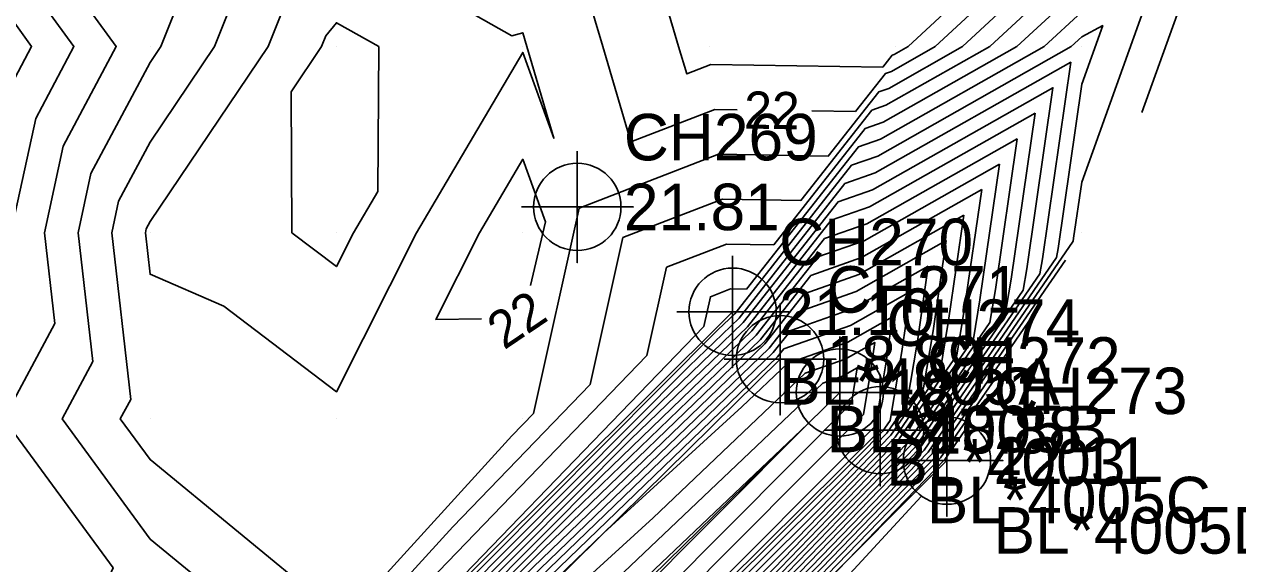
# Model space of a CAD drawing. Extents: x 2531902 to 2533249, y 715219 to 716099.
# Drawn here: x 2533033.2 to 2533098.4, y 715822.2 to 715851.2 of the extents above; entities that cross this region are included whole.
import ezdxf

# ---------------------------------------------------------------- set-up
doc = ezdxf.new("R2010")
doc.units = 0
for name, color, linetype in [('DTM Contours Major', 7, 'Continuous'), ('DTM Contours Major Text', 7, 'Continuous'), ('DTM Contours Minor', 7, 'Continuous'), ('Exist DTM Breakline', 7, 'Continuous'), ('Exist DTM Breakline Cogo Comment', 7, 'Continuous'), ('Exist DTM Breakline Cogo Elevation', 7, 'Continuous'), ('Exist DTM Breakline Cogo Number', 7, 'Continuous'), ('Exist DTM Breakline Cogo Point CELL', 7, 'Continuous'), ('Exist DTM Drainline', 7, 'Continuous'), ('Exist DTM Drainline Cogo Comment', 7, 'Continuous'), ('Exist DTM Drainline Cogo Elevation', 7, 'Continuous'), ('Exist DTM Drainline Cogo Number', 7, 'Continuous'), ('Exist DTM Drainline Cogo Point CELL', 7, 'Continuous'), ('Exist DTM QL2 LIDAR Elevation Point', 7, 'Continuous'), ('Exist DTM Regular Point CELL', 7, 'Continuous'), ('Exist DTM Regular Point Cogo Elevation', 7, 'Continuous'), ('Exist DTM Regular Point Cogo Number', 7, 'Continuous')]:
    doc.layers.add(name, color=color, linetype=linetype)

msp = doc.modelspace()

# ---------------------------------------------------------------- linework, layer by layer
at = {"layer": 'DTM Contours Major'}
for points in [[(2533075.512, 715846.541), (2533077.856, 715846.504), (2533079.467, 715848.554), (2533079.786, 715848.666), (2533082.141, 715850), (2533090, 715857.3), (2533095.009, 715860), (2533097.108, 715867.108), (2533098.179, 715870), (2533100, 715875.186), (2533111.816, 715879.234), (2533118.548, 715880.563)], [(2533041.774, 715810.454), (2533042.404, 715811.1), (2533043.161, 715818.289), (2533049.48, 715820), (2533040, 715827.811), (2533038.4, 715830), (2533038.956, 715831.044), (2533037.941, 715840), (2533038.308, 715841.692), (2533040, 715844.87), (2533043.452, 715850), (2533045.318, 715854.682), (2533049.57, 715860), (2533050, 715860.663), (2533051.38, 715861.38), (2533060, 715863.087), (2533062.327, 715860), (2533061.88, 715858.12), (2533064.295, 715850), (2533065.802, 715844.886), (2533070.3, 715846.623), (2533071.512, 715846.604)], [(2533055.198, 715819.396), (2533070.495, 715834.792), (2533071.376, 715835.643), (2533077.65, 715843.625), (2533079.056, 715844.119), (2533089.44, 715850), (2533090, 715850.52), (2533091.128, 715851.128), (2533090, 715847.981), (2533088.729, 715839.16), (2533088.647, 715838.672), (2533081.538, 715828.315), (2533066.066, 715812.328), (2533063.311, 715809.583)], [(2533057.677, 715840), (2533060, 715843.945), (2533061.222, 715840.578), (2533060.412, 715837.159)], [(2533085.587, 715843.684), (2533078.325, 715839.571), (2533075.832, 715838.696), (2533072.526, 715834.489), (2533062.673, 715824.977), (2533051.181, 715813.41), (2533041.576, 715804.106), (2533029.847, 715792.318), (2533029.205, 715791.695), (2533027.895, 715790.378), (2533015.561, 715777.627), (2533013.348, 715775.36)], [(2533082.375, 715831.659), (2533084.183, 715834.292), (2533084.535, 715836.387), (2533085.587, 715843.684)], [(2533057.787, 715835.38), (2533055.335, 715835.335), (2533057.677, 715840)], [(2533080.807, 715836.843), (2533077.595, 715835.024), (2533074.015, 715833.767), (2533073.676, 715833.335), (2533054.852, 715815.162), (2533052.148, 715812.44), (2533034.586, 715795.428), (2533030.67, 715791.493), (2533029.541, 715790.397), (2533029.097, 715789.95), (2533012.049, 715772.325), (2533009.123, 715768.142), (2533009.05, 715768.032)], [(2533048.953, 715798.969), (2533056.72, 715806.716), (2533058.104, 715808.153), (2533078.44, 715828.42), (2533079.316, 715829.326), (2533079.719, 715829.913), (2533080.342, 715833.615), (2533080.807, 715836.843)], [(2533083.724, 715829.377), (2533082.649, 715827.81), (2533076.89, 715821.859), (2533063.46, 715807.284), (2533061.198, 715804.899), (2533056.94, 715799.884), (2533056.737, 715799.66)], [(2533008.764, 715758.562), (2533009.843, 715760.678), (2533014.663, 715765.254), (2533014.672, 715765.262), (2533023.159, 715773.32), (2533037.158, 715784.95), (2533037.66, 715785.451), (2533038.413, 715786.237), (2533049.753, 715797.548), (2533059.385, 715807.549), (2533072.253, 715820.374), (2533080.039, 715828.42)]]:
    msp.add_lwpolyline(points, dxfattribs=at)
at = {"layer": 'DTM Contours Minor'}
for points in [[(2533029.47, 715797.174), (2533034.584, 715802), (2533044.323, 715811.978), (2533044.889, 715817.354), (2533050.003, 715818.738), (2533059.408, 715829.085), (2533060.57, 715830.291), (2533063.024, 715841.321), (2533070.513, 715844.213), (2533076.394, 715844.12), (2533079.104, 715847.569), (2533079.64, 715847.757), (2533083.601, 715850), (2533090, 715855.944), (2533097.525, 715860), (2533100, 715868.383)], [(2533032.179, 715798.448), (2533046.243, 715812.856), (2533046.618, 715816.418), (2533050.007, 715817.335), (2533056.239, 715824.192), (2533063.618, 715831.849), (2533065.373, 715839.735), (2533070.727, 715841.802), (2533074.931, 715841.736), (2533078.74, 715846.583), (2533079.494, 715846.847), (2533085.061, 715850), (2533090, 715854.588), (2533099.953, 715859.953)], [(2533067.676, 715852.324), (2533068.367, 715850), (2533068.798, 715848.536), (2533070.086, 715849.033), (2533079.318, 715848.888), (2533079.83, 715849.54), (2533079.932, 715849.576), (2533080.681, 715850), (2533090, 715858.655)], [(2533029.774, 715794.896), (2533048.162, 715813.734), (2533048.347, 715815.482), (2533050.01, 715815.933), (2533053.069, 715819.299), (2533066.666, 715833.407), (2533067.721, 715838.149), (2533070.941, 715839.392), (2533073.469, 715839.352), (2533078.377, 715845.597), (2533079.348, 715845.938), (2533086.52, 715850), (2533090, 715853.232), (2533097.012, 715857.012), (2533093.228, 715846.455)], [(2533030, 715800.68), (2533034.245, 715804.245), (2533039.393, 715809.104), (2533040.484, 715810.222), (2533041.432, 715819.225), (2533044.295, 715820), (2533040, 715823.539), (2533035.277, 715830), (2533036.919, 715833.081), (2533036.135, 715840), (2533036.825, 715843.175), (2533040, 715849.143), (2533040.577, 715850), (2533043.262, 715856.738)], [(2533030, 715804.336), (2533036.745, 715810), (2533033.616, 715816.384), (2533037.117, 715820), (2533038.009, 715821.991), (2533032.155, 715830), (2533034.882, 715835.118), (2533034.329, 715840), (2533035.341, 715844.659), (2533038.183, 715850), (2533034.175, 715855.527)], [(2533050, 715855.91), (2533047.374, 715852.626), (2533046.328, 715850), (2533040, 715840.598), (2533039.792, 715840.208), (2533039.747, 715840), (2533040, 715837.77), (2533043.949, 715836.051), (2533050, 715831.445), (2533054.295, 715840), (2533060, 715849.686), (2533061.673, 715845.079), (2533060.222, 715850), (2533060, 715850.748), (2533059.418, 715850.582), (2533050, 715855.91)], [(2533028.859, 715793.308), (2533049.964, 715814.518), (2533050.02, 715814.573), (2533051.407, 715815.969), (2533069.714, 715834.964), (2533070.069, 715836.563), (2533071.155, 715836.982), (2533072.007, 715836.969), (2533078.013, 715844.611), (2533079.202, 715845.028), (2533087.98, 715850), (2533090, 715851.876), (2533094.07, 715854.07), (2533090, 715842.716), (2533089.567, 715839.714), (2533089.539, 715839.548), (2533081.76, 715828.214), (2533064.829, 715810.719), (2533060.921, 715806.824), (2533041.394, 715786.547), (2533040.207, 715785.363), (2533038.711, 715783.801), (2533038.669, 715783.758), (2533033.901, 715779.797)], [(2533032.523, 715840), (2533033.857, 715846.143), (2533035.909, 715850), (2533033.015, 715853.991)], [(2533032.373, 715847.627), (2533033.636, 715850), (2533031.855, 715852.456)], [(2533047.563, 715847.563), (2533049.203, 715850), (2533049.43, 715850.57), (2533050, 715851.282), (2533052.267, 715850), (2533052.22, 715842.22), (2533050.913, 715840), (2533050, 715838.182), (2533047.612, 715840), (2533047.563, 715847.563)], [(2533029.188, 715792.978), (2533047.168, 715811.047), (2533050.407, 715814.185), (2533068.93, 715832.829), (2533071.606, 715835.412), (2533077.286, 715842.639), (2533078.91, 715843.209), (2533089.411, 715849.157), (2533087.89, 715838.605), (2533087.754, 715837.796), (2533081.316, 715828.416), (2533067.304, 715813.937), (2533060.409, 715807.066), (2533044.18, 715790.214), (2533039.609, 715785.654), (2533038.361, 715784.351), (2533038.165, 715784.155), (2533016.248, 715765.948)], [(2533029.353, 715792.813), (2533045.77, 715809.312), (2533050.6, 715813.991), (2533067.366, 715830.866), (2533071.836, 715835.181), (2533076.923, 715841.654), (2533078.764, 715842.3), (2533088.455, 715847.788), (2533087.051, 715838.051), (2533086.861, 715836.92), (2533081.093, 715828.517), (2533068.541, 715815.546), (2533060.153, 715807.187), (2533045.573, 715792.047), (2533039.31, 715785.8), (2533038.186, 715784.626), (2533037.914, 715784.354), (2533017.016, 715766.994)], [(2533019.064, 715769.102), (2533037.662, 715784.553), (2533038.011, 715784.901), (2533039.011, 715785.945), (2533046.967, 715793.881), (2533059.897, 715807.307), (2533069.778, 715817.156), (2533080.871, 715828.618), (2533085.968, 715836.044), (2533086.213, 715837.496), (2533087.499, 715846.42)], [(2533087.499, 715846.42), (2533078.617, 715841.39), (2533076.559, 715840.668), (2533072.066, 715834.951), (2533065.802, 715828.903), (2533050.794, 715813.798), (2533044.372, 715807.577), (2533029.518, 715792.648)], [(2533021.111, 715771.211), (2533037.41, 715784.751), (2533037.835, 715785.176), (2533038.712, 715786.091), (2533048.36, 715795.714), (2533059.641, 715807.428), (2533071.016, 715818.765), (2533080.649, 715828.719), (2533085.076, 715835.168), (2533085.374, 715836.942), (2533086.543, 715845.052)], [(2533086.543, 715845.052), (2533078.471, 715840.481), (2533076.196, 715839.682), (2533072.296, 715834.72), (2533064.238, 715826.94), (2533050.987, 715813.604), (2533042.974, 715805.841), (2533029.682, 715792.483)], [(2533025.207, 715775.429), (2533036.906, 715785.148), (2533037.485, 715785.726), (2533038.114, 715786.382), (2533051.147, 715799.382), (2533059.128, 715807.67), (2533073.49, 715821.983), (2533080.205, 715828.922), (2533083.29, 715833.416), (2533083.697, 715835.833), (2533084.631, 715842.315)], [(2533084.631, 715842.315), (2533078.179, 715838.662), (2533075.469, 715837.71), (2533072.756, 715834.258), (2533061.109, 715823.014), (2533051.374, 715813.216), (2533040.178, 715802.37), (2533030.011, 715792.153)], [(2533027.254, 715777.537), (2533036.655, 715785.347), (2533037.31, 715786.001), (2533037.815, 715786.528), (2533052.54, 715801.215), (2533058.872, 715807.791), (2533074.728, 715823.593), (2533079.983, 715829.023), (2533082.397, 715832.54), (2533082.858, 715835.279), (2533083.675, 715840.947)], [(2533083.675, 715840.947), (2533078.033, 715837.752), (2533075.106, 715836.724), (2533072.986, 715834.028), (2533059.545, 715821.051), (2533051.567, 715813.022), (2533038.78, 715800.635), (2533030.176, 715791.988)], [(2533029.302, 715779.646), (2533036.403, 715785.546), (2533037.135, 715786.276), (2533037.516, 715786.674), (2533053.933, 715803.049), (2533058.616, 715807.911), (2533075.965, 715825.202), (2533079.76, 715829.124), (2533081.504, 715831.665), (2533082.019, 715834.724), (2533082.719, 715839.579)], [(2533082.719, 715839.579), (2533077.887, 715836.843), (2533074.742, 715835.739), (2533073.216, 715833.797), (2533057.981, 715819.088), (2533051.761, 715812.828), (2533037.382, 715798.899), (2533030.341, 715791.823)], [(2533089.128, 715838.524), (2533081.982, 715828.113), (2533063.592, 715809.11), (2533061.177, 715806.704), (2533043.718, 715788.574), (2533040.95, 715785.525), (2533041.002, 715784.939), (2533040.368, 715784.644), (2533039.005, 715783.046), (2533032.907, 715774.504)], [(2533081.763, 715838.211), (2533077.741, 715835.933), (2533074.379, 715834.753), (2533073.446, 715833.566), (2533056.416, 715817.125), (2533051.954, 715812.634), (2533035.984, 715797.164), (2533030.505, 715791.658)], [(2533031.349, 715781.755), (2533036.151, 715785.744), (2533036.959, 715786.551), (2533037.217, 715786.819), (2533055.327, 715804.882), (2533058.36, 715808.032), (2533077.202, 715826.811), (2533079.538, 715829.225), (2533080.612, 715830.789), (2533081.181, 715834.17), (2533081.763, 715838.211)], [(2533087.327, 715835.475), (2533082.204, 715828.012), (2533062.354, 715807.5), (2533061.434, 715806.583), (2533054.775, 715799.669), (2533042.737, 715786.408), (2533042.962, 715783.863), (2533040.204, 715782.579), (2533039.448, 715781.692), (2533033.848, 715773.848), (2533034.441, 715770), (2533037.497, 715767.497), (2533039.733, 715760), (2533030, 715753.287), (2533027.092, 715752.908), (2533020, 715752.921), (2533010.485, 715746.227), (2533020, 715741.25), (2533021.25, 715740), (2533025.743, 715735.743), (2533027.791, 715735.581), (2533030.365, 715736.068)], [(2533033.188, 715793.693), (2533052.341, 715812.246), (2533053.288, 715813.199), (2533064.344, 715823.873), (2533071.763, 715830.647), (2533074.213, 715832.978), (2533077.449, 715834.114), (2533079.851, 715835.474), (2533079.503, 715833.061), (2533078.925, 715829.628), (2533058.873, 715809.446), (2533057.785, 715808.352), (2533043.525, 715793.999), (2533036.619, 715787.111), (2533036.609, 715787.1), (2533035.648, 715786.142), (2533035.444, 715785.972), (2533033.02, 715783.671)], [(2533015.773, 715771.784), (2533022.151, 715780.652), (2533025.807, 715785.88), (2533029.577, 715789.779), (2533029.676, 715789.877), (2533030.999, 715791.163), (2533031.79, 715791.958), (2533042.258, 715802.098), (2533049.87, 715808.942), (2533052.953, 715811.863), (2533066.991, 715824.68), (2533075.158, 715832.451), (2533077.303, 715833.205), (2533078.895, 715834.106), (2533078.665, 715832.506), (2533078.282, 715830.231), (2533064.99, 715816.854), (2533057.137, 715808.963), (2533041.884, 715793.61), (2533035.994, 715787.69), (2533035.267, 715786.958), (2533034.852, 715786.542), (2533020.715, 715773.614), (2533015.773, 715771.784)], [(2533030.23, 715789.352), (2533031.368, 715790.375), (2533031.741, 715790.725), (2533044.287, 715802.006), (2533054.056, 715811.26), (2533062.22, 715818.714), (2533076.103, 715831.925), (2533077.157, 715832.295), (2533077.939, 715832.738), (2533077.826, 715831.952), (2533077.638, 715830.834), (2533071.107, 715824.261), (2533056.488, 715809.573), (2533047.618, 715800.644), (2533035.342, 715788.307), (2533034.873, 715787.835), (2533034.004, 715786.962), (2533024.831, 715778.573), (2533021.624, 715777.386), (2533030.23, 715789.352)], [(2533085.525, 715832.426), (2533082.426, 715827.911), (2533065.833, 715810.764), (2533062.109, 715806.723), (2533061.482, 715806.062), (2533060.302, 715804.672), (2533044.524, 715787.292), (2533044.922, 715782.787), (2533040.041, 715780.515), (2533039.89, 715780.338), (2533038.773, 715778.773), (2533040, 715770.808), (2533040.103, 715770), (2533043.032, 715763.032)], [(2533031.424, 715788.479), (2533031.947, 715788.948), (2533033.074, 715790.008), (2533038.704, 715795.07), (2533055.158, 715810.656), (2533057.448, 715812.747), (2533075.297, 715829.733), (2533055.84, 715810.183), (2533053.352, 715807.678), (2533034.69, 715788.923), (2533034.48, 715788.711), (2533033.156, 715787.382), (2533028.947, 715783.532), (2533027.476, 715782.988), (2533031.424, 715788.479)], [(2533081.379, 715825.827), (2533064.81, 715807.845), (2533060.913, 715803.736), (2533053.578, 715795.096), (2533048.098, 715789.059), (2533048.842, 715780.636), (2533047.477, 715780), (2533049.392, 715770.608), (2533049.469, 715770), (2533049.626, 715769.626)]]:
    msp.add_lwpolyline(points, dxfattribs=at)
at = {"layer": 'Exist DTM Breakline'}
for points in [[(2533071.263, 715835.756), (2533026.299, 715790.948), (2533003.355, 715768.576), (2532992.757, 715767.273), (2532984.347, 715757.832), (2532975.467, 715747.036), (2532972.43, 715743.961)], [(2533073.808, 715833.204), (2533029.714, 715789.73), (2533006.807, 715767.161), (2532991.54, 715751.848), (2532990.629, 715741.375)], [(2533079.183, 715829.387), (2533035.625, 715786.159), (2533002.978, 715754.978), (2532999.93, 715740.509), (2532990.629, 715741.375)], [(2533082.767, 715827.756), (2533038.809, 715783.648), (2533015.193, 715765.12), (2533008.042, 715745.259), (2533013.01, 715727.955)]]:
    msp.add_lwpolyline(points, dxfattribs=at)
at = {"layer": 'Exist DTM Breakline Cogo Point CELL'}
for points in [[(2533071.263, 715838.756), (2533071.263, 715832.756), (2533071.263, 715835.756), (2533074.263, 715835.756), (2533068.263, 715835.756)], [(2533073.808, 715836.204), (2533073.808, 715830.204), (2533073.808, 715833.204), (2533076.808, 715833.204), (2533070.808, 715833.204)], [(2533079.183, 715832.387), (2533079.183, 715826.387), (2533079.183, 715829.387), (2533082.183, 715829.387), (2533076.183, 715829.387)], [(2533082.767, 715830.756), (2533082.767, 715824.756), (2533082.767, 715827.756), (2533085.767, 715827.756), (2533079.767, 715827.756)]]:
    msp.add_lwpolyline(points, dxfattribs=at)
for centre in [(2533071.263, 715835.756), (2533073.808, 715833.204), (2533079.183, 715829.387), (2533082.767, 715827.756)]:
    msp.add_circle(centre, 2.344, dxfattribs=at)
at = {"layer": 'Exist DTM Drainline'}
msp.add_lwpolyline([(2533077.016, 715831.416), (2533032.437, 715787.738), (2533010.445, 715766.684), (2532997.007, 715751.307)], dxfattribs=at)
at = {"layer": 'Exist DTM Drainline Cogo Point CELL'}
msp.add_lwpolyline([(2533077.016, 715834.416), (2533077.016, 715828.416), (2533077.016, 715831.416), (2533080.016, 715831.416), (2533074.016, 715831.416)], dxfattribs=at)
msp.add_circle((2533077.016, 715831.416), 2.344, dxfattribs=at)
at = {"layer": 'Exist DTM QL2 LIDAR Elevation Point'}
for p, q in [((2533040, 715850), (2533040, 715850)), ((2533050, 715850), (2533050, 715850)), ((2533060, 715850), (2533060, 715850)), ((2533070, 715850), (2533070, 715850)), ((2533080, 715850), (2533080, 715850)), ((2533090, 715850), (2533090, 715850)), ((2533040, 715840), (2533040, 715840)), ((2533050, 715840), (2533050, 715840)), ((2533060, 715840), (2533060, 715840)), ((2533090, 715840), (2533090, 715840)), ((2533040, 715830), (2533040, 715830)), ((2533050, 715830), (2533050, 715830)), ((2533060, 715830), (2533060, 715830))]:
    msp.add_line(p, q, dxfattribs=at)
at = {"layer": 'Exist DTM Regular Point CELL'}
msp.add_lwpolyline([(2533062.928, 715844.386), (2533062.928, 715838.386), (2533062.928, 715841.386), (2533065.928, 715841.386), (2533059.928, 715841.386)], dxfattribs=at)
msp.add_circle((2533062.928, 715841.386), 2.344, dxfattribs=at)

# ---------------------------------------------------------------- texts
at = {"layer": 'DTM Contours Major Text'}
for s, rotation, p in [('22', 359.09872, (2533071.866, 715845.598)), ('22', 34.13595, (2533058.999, 715833.674)), ('20', 234.20039, (2533081.385, 715831.917))]:
    msp.add_text(s, height=2, rotation=rotation, dxfattribs=at).set_placement(p)
at = {"layer": 'Exist DTM Breakline Cogo Comment'}
for s, p in [('BL*4005A', (2533073.763, 715830.756)), ('BL*4005B', (2533076.308, 715828.204)), ('BL*4005C', (2533081.683, 715824.387)), ('BL*4005D', (2533085.267, 715822.756))]:
    msp.add_text(s, height=2.5, dxfattribs=at).set_placement(p)
at = {"layer": 'Exist DTM Breakline Cogo Elevation'}
for s, p in [('21.10', (2533073.763, 715834.506)), ('18.89', (2533076.308, 715831.954)), ('18.88', (2533081.683, 715828.137)), ('22.11', (2533085.267, 715826.506))]:
    msp.add_text(s, height=2.5, dxfattribs=at).set_placement(p)
at = {"layer": 'Exist DTM Breakline Cogo Number'}
for s, p in [('CH270', (2533073.763, 715838.256)), ('CH271', (2533076.308, 715835.704)), ('CH272', (2533081.683, 715831.887)), ('CH273', (2533085.267, 715830.256))]:
    msp.add_text(s, height=2.5, dxfattribs=at).set_placement(p)
at = {"layer": 'Exist DTM Drainline Cogo Comment'}
msp.add_text('BL*4003', height=2.5, dxfattribs=at).set_placement((2533079.516, 715826.416))
at = {"layer": 'Exist DTM Drainline Cogo Elevation'}
msp.add_text('18.21', height=2.5, dxfattribs=at).set_placement((2533079.516, 715830.166))
at = {"layer": 'Exist DTM Drainline Cogo Number'}
msp.add_text('CH274', height=2.5, dxfattribs=at).set_placement((2533079.516, 715833.916))
at = {"layer": 'Exist DTM Regular Point Cogo Elevation'}
msp.add_text('21.81', height=2.5, dxfattribs=at).set_placement((2533065.428, 715840.136))
at = {"layer": 'Exist DTM Regular Point Cogo Number'}
msp.add_text('CH269', height=2.5, dxfattribs=at).set_placement((2533065.428, 715843.886))

doc.saveas('drawing.dxf')
